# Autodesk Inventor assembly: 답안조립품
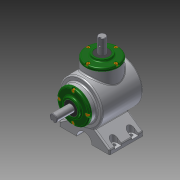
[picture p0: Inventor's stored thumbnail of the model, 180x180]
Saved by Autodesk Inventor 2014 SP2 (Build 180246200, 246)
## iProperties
Created: 2017-04
Part Number: 답안조립품
Document SubType Name: Assembly
Designer: 거성
Author: 거성
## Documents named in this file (14)
- C:\Users\거성\Desktop\470408V1017\답안조립품.iam
- C:\Users\거성\Desktop\470408V1017\본체.ipt
- C:\Users\거성\Desktop\470408V1017\커버.ipt
- C:\Users\거성\Desktop\470408V1017\오일실 17 32 8.ipt
- C:\Users\거성\Desktop\470408V1017\베어링 6203.ipt
- C:\Users\거성\Desktop\470408V1017\메인 축.ipt
- 메인 축.ipt
- C:\Users\거성\Desktop\470408V1017\메인 베벨기어.ipt
- C:\Users\거성\Desktop\470408V1017\키 5x5.ipt
- C:\Users\거성\Desktop\470408V1017\서브 축.ipt
- 서브 축.ipt
- C:\Users\거성\Desktop\470408V1017\서브 베벨기어.ipt
- C:\Users\거성\Desktop\470408V1017\키 4x4.ipt
- C:\Users\거성\Desktop\470408V1017\볼트 M4.ipt
